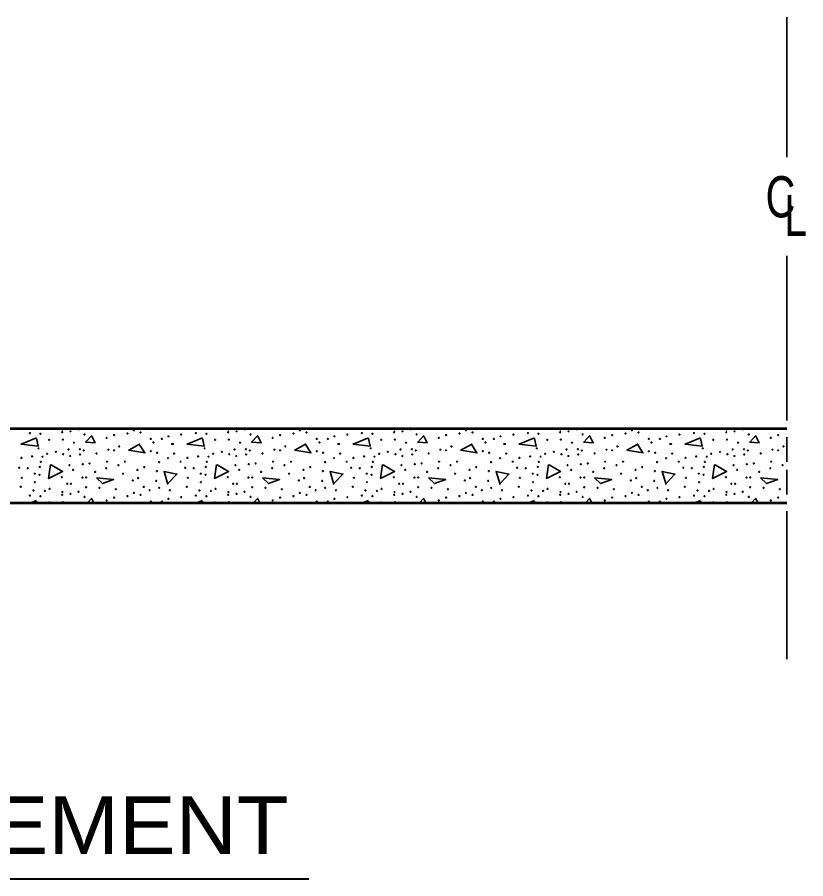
# Model space of a CAD drawing. Extents: x -89 to 766, y -60 to 484.
# Drawn here: x 140.2 to 197.7, y 231.2 to 294 of the extents above; entities that cross this region are included whole.
import ezdxf
from ezdxf.enums import TextEntityAlignment as Align

# ---------------------------------------------------------------- set-up
doc = ezdxf.new("R2010")
doc.units = 0
doc.header["$LTSCALE"] = 1.1
doc.layers.add('1', color=7, linetype='Continuous', lineweight=35)

msp = doc.modelspace()

# ---------------------------------------------------------------- linework, layer by layer
at = {"layer": '1'}
for p, q in [((196.323, 283.848), (196.323, 294.048)), ((196.323, 264.648), (196.323, 276.648)), ((196.323, 263.448), (196.323, 261.648)), ((196.323, 261.048), (196.323, 259.248)), ((141.648, 258.827), (141.204, 258.648)), ((141.676, 258.648), (141.648, 258.779)), ((145.68, 258.995), (145.35, 258.648)), ((145.829, 258.648), (145.68, 258.947)), ((153.744, 258.827), (153.3, 258.648)), ((153.772, 258.648), (153.744, 258.779)), ((157.776, 258.995), (157.446, 258.648)), ((157.925, 258.648), (157.776, 258.947)), ((165.84, 258.827), (165.396, 258.648)), ((165.868, 258.648), (165.84, 258.779)), ((169.872, 258.995), (169.542, 258.648)), ((170.021, 258.648), (169.872, 258.947)), ((177.936, 258.827), (177.492, 258.648)), ((177.964, 258.648), (177.936, 258.779)), ((181.968, 258.995), (181.638, 258.648)), ((182.117, 258.648), (181.968, 258.947)), ((190.032, 258.827), (189.588, 258.648)), ((190.06, 258.648), (190.032, 258.779)), ((194.064, 258.995), (193.734, 258.648)), ((194.213, 258.648), (194.064, 258.947)), ((196.323, 258.048), (196.323, 247.248))]:
    msp.add_line(p, q, dxfattribs=at)
at = {"layer": '1', "lineweight": 40}
msp.add_line((79.824, 231.246), (161.496, 231.246), dxfattribs=at)
at = {"layer": '1', "lineweight": 53}
msp.add_lwpolyline([(196.323, 264.048), (110.523, 264.048), (110.523, 261.648), (110.523, 258.648), (196.323, 258.648)], dxfattribs=at)
at = {"layer": '1'}
for points in [[(141.648, 263.387), (140.52, 262.931), (141.768, 262.787), (141.648, 263.339)], [(145.68, 263.555), (145.224, 263.075), (145.92, 263.027), (145.68, 263.507)], [(153.744, 263.387), (152.616, 262.931), (153.864, 262.787), (153.744, 263.339)], [(157.776, 263.555), (157.32, 263.075), (158.016, 263.027), (157.776, 263.507)], [(165.84, 263.387), (164.712, 262.931), (165.96, 262.787), (165.84, 263.339)], [(169.872, 263.555), (169.416, 263.075), (170.112, 263.027), (169.872, 263.507)], [(177.936, 263.387), (176.808, 262.931), (178.056, 262.787), (177.936, 263.339)], [(181.968, 263.555), (181.512, 263.075), (182.208, 263.027), (181.968, 263.507)], [(190.032, 263.387), (188.904, 262.931), (190.152, 262.787), (190.032, 263.339)], [(194.064, 263.555), (193.608, 263.075), (194.304, 263.027), (194.064, 263.507)], [(149.16, 262.931), (148.368, 262.499), (149.544, 262.283), (149.112, 262.955)], [(161.256, 262.931), (160.464, 262.499), (161.64, 262.283), (161.208, 262.955)], [(173.352, 262.931), (172.56, 262.499), (173.736, 262.283), (173.304, 262.955)], [(185.448, 262.931), (184.656, 262.499), (185.832, 262.283), (185.4, 262.955)], [(142.704, 261.419), (143.544, 260.939), (142.512, 260.435), (142.656, 261.443)], [(154.8, 261.419), (155.64, 260.939), (154.608, 260.435), (154.752, 261.443)], [(166.896, 261.419), (167.736, 260.939), (166.704, 260.435), (166.848, 261.443)], [(178.992, 261.419), (179.832, 260.939), (178.8, 260.435), (178.944, 261.443)], [(191.088, 261.419), (191.928, 260.939), (190.896, 260.435), (191.04, 261.443)], [(151.224, 259.979), (150.936, 260.939), (151.872, 260.747), (151.2, 260.027)], [(163.32, 259.979), (163.032, 260.939), (163.968, 260.747), (163.296, 260.027)], [(175.416, 259.979), (175.128, 260.939), (176.064, 260.747), (175.392, 260.027)], [(187.512, 259.979), (187.224, 260.939), (188.16, 260.747), (187.488, 260.027)]]:
    msp.add_lwpolyline(points, dxfattribs=at)
for points in [[(146.016, 260.483), (147.264, 260.339), (146.448, 260.051)], [(158.112, 260.483), (159.36, 260.339), (158.544, 260.051)], [(170.208, 260.483), (171.456, 260.339), (170.64, 260.051)], [(182.304, 260.483), (183.552, 260.339), (182.736, 260.051)], [(194.4, 260.483), (195.648, 260.339), (194.832, 260.051)]]:
    msp.add_lwpolyline(points, close=True, dxfattribs=at)
for centre in [(143.519, 263.799), (143.535, 264), (144.123, 263.862), (144.712, 264.016), (148.745, 263.936), (149.222, 263.783), (155.615, 263.799), (155.631, 264), (156.219, 263.862), (156.808, 264.016), (160.841, 263.936), (161.318, 263.783), (167.711, 263.799), (167.727, 264), (168.315, 263.862), (168.904, 264.016), (172.937, 263.936), (173.414, 263.783), (179.807, 263.799), (179.823, 264), (180.411, 263.862), (181, 264.016), (185.033, 263.936), (185.51, 263.783), (191.903, 263.799), (191.919, 264), (192.507, 263.862), (193.096, 264.016), (141.165, 263.735), (141.929, 263.687), (142.565, 263.242), (143.567, 263.258), (145.15, 263.64), (146.757, 263.385), (147.297, 263.592), (148.268, 263.703), (149.969, 263.306), (150.78, 263.306), (151.257, 263.497), (152.196, 263.624), (153.261, 263.735), (154.025, 263.687), (154.661, 263.242), (155.663, 263.258), (157.246, 263.64), (158.853, 263.385), (159.393, 263.592), (160.364, 263.703), (162.065, 263.306), (162.876, 263.306), (163.353, 263.497), (164.292, 263.624), (165.357, 263.735), (166.121, 263.687), (166.757, 263.242), (167.759, 263.258), (169.342, 263.64), (170.949, 263.385), (171.489, 263.592), (172.46, 263.703), (174.161, 263.306), (174.972, 263.306), (175.449, 263.497), (176.388, 263.624), (177.453, 263.735), (178.217, 263.687), (178.853, 263.242), (179.855, 263.258), (181.438, 263.64), (183.045, 263.385), (183.585, 263.592), (184.556, 263.703), (186.257, 263.306), (187.068, 263.306), (187.545, 263.497), (188.484, 263.624), (189.549, 263.735), (190.313, 263.687), (190.949, 263.242), (191.951, 263.258), (193.534, 263.64), (195.141, 263.385), (195.681, 263.592), (141.801, 262.622), (143.98, 262.542), (144.378, 263.035), (144.807, 262.558), (146.884, 262.526), (147.679, 262.765), (150.16, 263.051), (151.528, 262.94), (151.591, 262.94), (153.897, 262.622), (156.076, 262.542), (156.474, 263.035), (156.903, 262.558), (158.98, 262.526), (159.775, 262.765), (162.256, 263.051), (163.624, 262.94), (163.687, 262.94), (165.993, 262.622), (168.172, 262.542), (168.57, 263.035), (168.999, 262.558), (171.076, 262.526), (171.871, 262.765), (174.352, 263.051), (175.72, 262.94), (175.783, 262.94), (178.089, 262.622), (180.268, 262.542), (180.666, 263.035), (181.095, 262.558), (183.172, 262.526), (183.967, 262.765), (186.448, 263.051), (187.816, 262.94), (187.879, 262.94), (190.185, 262.622), (192.364, 262.542), (192.762, 263.035), (193.191, 262.558), (195.268, 262.526), (196.063, 262.765), (140.545, 261.922), (141.324, 262.033), (142.088, 262.017), (142.422, 262.224), (143.058, 262.367), (143.599, 262.192), (144.108, 262.065), (144.823, 262.176), (145.087, 262.463), (146.025, 262.256), (147.297, 262.478), (149.969, 262.415), (150.43, 262.303), (151.226, 261.906), (151.671, 262.24), (152.641, 261.922), (153.42, 262.033), (154.184, 262.017), (154.518, 262.224), (155.154, 262.367), (155.695, 262.192), (156.204, 262.065), (156.919, 262.176), (157.183, 262.463), (158.121, 262.256), (159.393, 262.478), (162.065, 262.415), (162.526, 262.303), (163.322, 261.906), (163.767, 262.24), (164.737, 261.922), (165.516, 262.033), (166.28, 262.017), (166.614, 262.224), (167.25, 262.367), (167.791, 262.192), (168.3, 262.065), (169.015, 262.176), (169.279, 262.463), (170.217, 262.256), (171.489, 262.478), (174.161, 262.415), (174.622, 262.303), (175.418, 261.906), (175.863, 262.24), (176.833, 261.922), (177.612, 262.033), (178.376, 262.017), (178.71, 262.224), (179.346, 262.367), (179.887, 262.192), (180.396, 262.065), (181.111, 262.176), (181.375, 262.463), (182.313, 262.256), (183.585, 262.478), (186.257, 262.415), (186.718, 262.303), (187.514, 261.906), (187.959, 262.24), (188.929, 261.922), (189.708, 262.033), (190.472, 262.017), (190.806, 262.224), (191.442, 262.367), (191.983, 262.192), (192.492, 262.065), (193.207, 262.176), (193.471, 262.463), (194.409, 262.256), (195.681, 262.478), (141.881, 261.269), (141.961, 261.635), (144.044, 261.397), (145.014, 261.46), (145.516, 261.524), (146.788, 261.651), (147.615, 261.397), (148.093, 261.651), (149.492, 261.253), (150.574, 261.619), (152.148, 261.651), (153.977, 261.269), (154.057, 261.635), (156.14, 261.397), (157.11, 261.46), (157.612, 261.524), (158.884, 261.651), (159.711, 261.397), (160.189, 261.651), (161.588, 261.253), (162.67, 261.619), (164.244, 261.651), (166.073, 261.269), (166.153, 261.635), (168.236, 261.397), (169.206, 261.46), (169.708, 261.524), (170.98, 261.651), (171.807, 261.397), (172.285, 261.651), (173.684, 261.253), (174.766, 261.619), (176.34, 261.651), (178.169, 261.269), (178.249, 261.635), (180.332, 261.397), (181.302, 261.46), (181.804, 261.524), (183.076, 261.651), (183.903, 261.397), (184.381, 261.651), (185.78, 261.253), (186.862, 261.619), (188.436, 261.651), (190.265, 261.269), (190.345, 261.635), (192.428, 261.397), (193.398, 261.46), (193.9, 261.524), (195.172, 261.651), (195.999, 261.397), (140.386, 261.206), (141.006, 261.174), (141.515, 260.776), (141.865, 260.697), (144.314, 261.047), (145.914, 260.903), (146.725, 261.174), (147.949, 260.776), (148.999, 261.047), (150.415, 260.967), (152.482, 261.206), (153.102, 261.174), (153.611, 260.776), (153.961, 260.697), (156.41, 261.047), (158.01, 260.903), (158.821, 261.174), (160.045, 260.776), (161.095, 261.047), (162.511, 260.967), (164.578, 261.206), (165.198, 261.174), (165.707, 260.776), (166.057, 260.697), (168.506, 261.047), (170.106, 260.903), (170.917, 261.174), (172.141, 260.776), (173.191, 261.047), (174.607, 260.967), (176.674, 261.206), (177.294, 261.174), (177.803, 260.776), (178.153, 260.697), (180.602, 261.047), (182.202, 260.903), (183.013, 261.174), (184.237, 260.776), (185.287, 261.047), (186.703, 260.967), (188.77, 261.206), (189.39, 261.174), (189.899, 260.776), (190.249, 260.697), (192.698, 261.047), (194.298, 260.903), (195.109, 261.174), (140.577, 260.474), (141.531, 260.156), (143.487, 260.522), (143.885, 260.044), (144.155, 260.044), (144.99, 260.487), (145.262, 260.506), (148.665, 260.283), (149.047, 260.458), (150.367, 260.251), (152.673, 260.474), (153.627, 260.156), (155.583, 260.522), (155.981, 260.044), (156.251, 260.044), (157.086, 260.487), (157.358, 260.506), (160.761, 260.283), (161.143, 260.458), (162.463, 260.251), (164.769, 260.474), (165.723, 260.156), (167.679, 260.522), (168.077, 260.044), (168.347, 260.044), (169.182, 260.487), (169.454, 260.506), (172.857, 260.283), (173.239, 260.458), (174.559, 260.251), (176.865, 260.474), (177.819, 260.156), (179.775, 260.522), (180.173, 260.044), (180.443, 260.044), (181.278, 260.487), (181.55, 260.506), (184.953, 260.283), (185.335, 260.458), (186.655, 260.251), (188.961, 260.474), (189.915, 260.156), (191.871, 260.522), (192.269, 260.044), (192.539, 260.044), (193.374, 260.487), (193.646, 260.506), (140.497, 259.822), (141.42, 259.551), (142.263, 259.519), (142.597, 259.663), (143.535, 259.44), (144.712, 259.456), (145.262, 259.79), (146.232, 259.742), (147.425, 259.647), (148.745, 259.376), (149.46, 259.806), (149.89, 259.567), (150.589, 259.742), (151.369, 259.567), (152.593, 259.822), (153.516, 259.551), (154.359, 259.519), (154.693, 259.663), (155.631, 259.44), (156.808, 259.456), (157.358, 259.79), (158.328, 259.742), (159.521, 259.647), (160.841, 259.376), (161.556, 259.806), (161.986, 259.567), (162.685, 259.742), (163.465, 259.567), (164.689, 259.822), (165.612, 259.551), (166.455, 259.519), (166.789, 259.663), (167.727, 259.44), (168.904, 259.456), (169.454, 259.79), (170.424, 259.742), (171.617, 259.647), (172.937, 259.376), (173.652, 259.806), (174.082, 259.567), (174.781, 259.742), (175.561, 259.567), (176.785, 259.822), (177.708, 259.551), (178.551, 259.519), (178.885, 259.663), (179.823, 259.44), (181, 259.456), (181.55, 259.79), (182.52, 259.742), (183.713, 259.647), (185.033, 259.376), (185.748, 259.806), (186.178, 259.567), (186.877, 259.742), (187.657, 259.567), (188.881, 259.822), (189.804, 259.551), (190.647, 259.519), (190.981, 259.663), (191.919, 259.44), (193.096, 259.456), (193.646, 259.79), (194.616, 259.742), (195.809, 259.647), (141.165, 259.175), (141.929, 259.127), (143.519, 259.239), (144.123, 259.302), (145.15, 259.08), (146.757, 258.825), (147.297, 259.032), (148.268, 259.143), (149.222, 259.223), (149.969, 258.746), (150.78, 258.746), (151.257, 258.937), (152.196, 259.064), (153.261, 259.175), (154.025, 259.127), (155.615, 259.239), (156.219, 259.302), (157.246, 259.08), (158.853, 258.825), (159.393, 259.032), (160.364, 259.143), (161.318, 259.223), (162.065, 258.746), (162.876, 258.746), (163.353, 258.937), (164.292, 259.064), (165.357, 259.175), (166.121, 259.127), (167.711, 259.239), (168.315, 259.302), (169.342, 259.08), (170.949, 258.825), (171.489, 259.032), (172.46, 259.143), (173.414, 259.223), (174.161, 258.746), (174.972, 258.746), (175.449, 258.937), (176.388, 259.064), (177.453, 259.175), (178.217, 259.127), (179.807, 259.239), (180.411, 259.302), (181.438, 259.08), (183.045, 258.825), (183.585, 259.032), (184.556, 259.143), (185.51, 259.223), (186.257, 258.746), (187.068, 258.746), (187.545, 258.937), (188.484, 259.064), (189.549, 259.175), (190.313, 259.127), (191.903, 259.239), (192.507, 259.302), (193.534, 259.08), (195.141, 258.825), (195.681, 259.032), (142.565, 258.682), (143.567, 258.698), (154.661, 258.682), (155.663, 258.698), (166.757, 258.682), (167.759, 258.698), (178.853, 258.682), (179.855, 258.698), (190.949, 258.682), (191.951, 258.698)]:
    msp.add_circle(centre, 0.0318, dxfattribs=at)
for centre, start, end in [((142.263, 264.079), 262.28656, 277.71344), ((154.359, 264.079), 262.28656, 277.71344), ((166.455, 264.079), 262.28656, 277.71344), ((178.551, 264.079), 262.28656, 277.71344), ((190.647, 264.079), 262.28656, 277.71344), ((196.333, 260.776), 109.58284, 250.41716)]:
    msp.add_arc(centre, 0.0318, start, end, dxfattribs=at)

# ---------------------------------------------------------------- texts
at = {"layer": '1', "width": 0.75}
for s, p in [('C', (194.76, 279.459)), ('L', (196.117, 278.101))]:
    msp.add_text(s, height=3, dxfattribs=at).set_placement(p)
at = {"layer": '1', "width": 1.1}
msp.add_text('DELINEATOR PLACEMENT', height=4.2, dxfattribs=at).set_placement((120.534, 233.046), align=Align.CENTER)

doc.saveas('drawing.dxf')
